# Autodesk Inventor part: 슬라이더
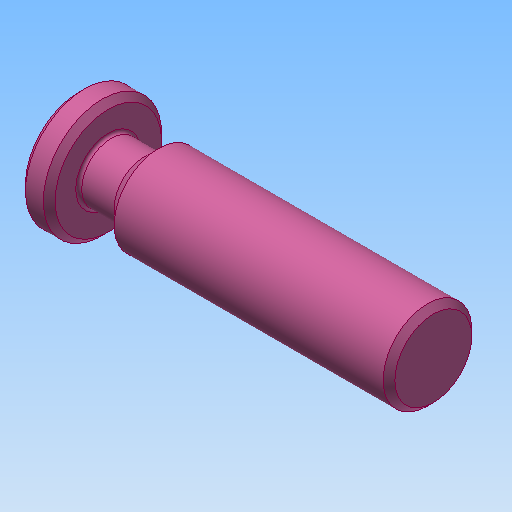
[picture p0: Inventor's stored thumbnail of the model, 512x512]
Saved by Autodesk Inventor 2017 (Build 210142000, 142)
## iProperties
Created: 2016-05
Part Number: 슬라이더
Document SubType Name: Modeling
Designer: mduedu
Density: 7.86 g/cm^3
Material: 강철, 연강
Appearance: 분홍색
Author: mduedu
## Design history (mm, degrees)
sketch "스케치1"
  geometry: L1 (-7.5, 0)-(52.5, 0); L2 (52.5, 0)-(52.5, 7.5); L3 (52.5, 7.5)-(0, 7.5); L4 (-7.5, 0)-(-7.5, 10); L5 (-7.5, 10)-(-2.5, 10); L6 (-2.5, 10)-(-2.5, 5); L7 (-2.5, 5)-(3.5, 5); L8 (3.5, 5)-(6, 7.5); A1 r 7.5 centre (0, 0) between (0, 7.5) and (-7.5, 0); 1 further point
  constraints: 16 end point, 3 perpendicular, 2 horizontal, 2 parallel, 2 point on circle, 2 point on line, 2 tangent, 1 centre point, 1 coincident
  dimensions: "d0" = 15 diameter of A1; "d1" = 60 distance of L1.start L1.end; "d19" = 20 diameter of L5 L1; "d20" = 10 diameter of L7 L1; "d21" = 5 distance of L4.end L5.end; "d22" = 135 deg angle of L8 L7; "d23" = 6 distance of L6.end L7.end
revolve "회전1" stored, may be unused: angle "d4" = 90 deg
chamfer "모따기2" distance "d24" = 1; stored, may be unused: second distance "d25" = 2, angle "d26" = 45 deg
fillet "모깎기1" dims "d27" = 0.5
node "솔리드1"
